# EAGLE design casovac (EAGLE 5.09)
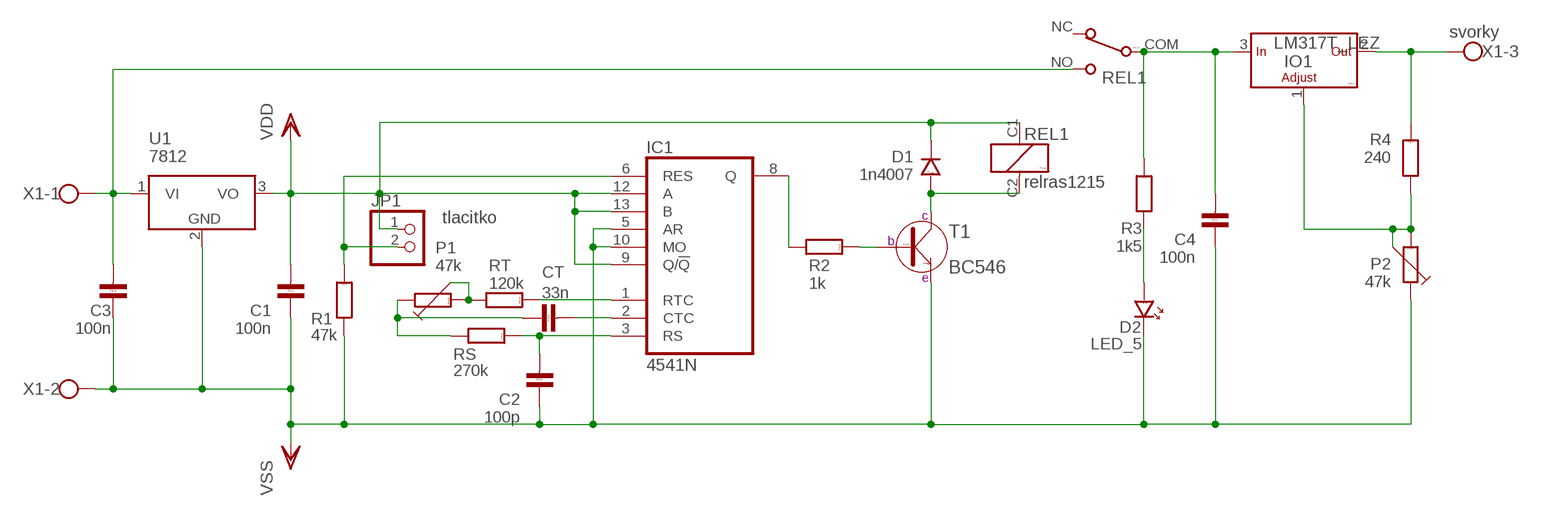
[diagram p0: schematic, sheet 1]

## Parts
C1  100n  C-KERAMIK_5  [C-5]
C2  100p  C-KERAMIK_5  [C-5]
C3  100n  C-KERAMIK_5  [C-5]
C4  100n  C-KERAMIK_5  [C-5]
CT  33n  C-KERAMIK_5  [C-5]
D1  1n4007  D_10  [D-10]
D2  LED_5  [LED_5]
IC1  4541N  [DIL14]
IO1  LM317T_LEZ  [TO-220]
JP1  tlacitko  PINHD-1X2  [1X02]
P1  47k  PT-10_V-LEZ  [PT10V]
P2  47k  PT-10_V-LEZ  [PT10V]
R1  47k  R_7,5  [R-7,5]
R2  1k  R_7,5  [R-7,5]
R3  1k5  R_7,5  [R-7,5]
R4  240  R_7,5  [R-7,5]
REL1  relras1215  RELRAS15  [RELE_RAS]
RS  270k  R_7,5  [R-7,5]
RT  120k  R_7,5  [R-7,5]
T1  BC546  [TO-92]
U1  7812  [TO-220S]
X1  svorky  W237-103  [W237-103]

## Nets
N$1: D1.A REL1.C2(RE:C2) T1.1(C)
N$2: IC1.6(RES) JP1.2 R1.2
N$3: IC1.8(Q) R2.1
N$4: R2.2 T1.2(B)
N$5: C2.2 IC1.3(RS) RS.2
N$6: IC1.1(RTC) RT.2
N$7: P1.2 P1.3 RT.1
N$8: CT.2 IC1.2(CTC)
N$9: CT.1 P1.1 RS.1
N$10: C3.2 REL1.NO(SW:NO) U1.1(VI) X1.1
N$11: C4.2 IO1.3(IN) R3.2 REL1.COM(SW:COM)
N$12: D2.A R3.1
N$13: IO1.2(OUT) R4.2 X1.3
N$14: IO1.1(ADJ) P2.2 P2.3 R4.1
VDD: C1.2 D1.K IC1.9(Q/!Q) IC1.12(A) IC1.13(B) JP1.1 REL1.C1(RE:C1) U1.3(VO)
VSS: C1.1 C2.1 C3.1 C4.1 D2.K IC1.5(AR) IC1.10(MO) P2.1 R1.1 T1.3(E) U1.2(GND) X1.2
Unconnected: REL1.NC(SW:NC)

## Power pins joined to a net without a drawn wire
VDD: IC1.14(VDD)
VSS: IC1.7(VSS)

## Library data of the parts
C1-C4 CT = #PaJa_21:C-KERAMIK: Kondenzator - keramicky
D1 = #PaJa_21:D: Dioda - univerzální
D2 = #PaJa_21:LED: LED - jednobarevna
IC1 = 45xx:4541: OSCILLATOR/PROGRAMMABLE TIMER
IO1 = #PaJa_21:LM317T: Stabilizator - s nastavitelnym napetim - 1,5A
JP1 = pinhead:PINHD-1X2: PIN HEADER
P1 P2 = #PaJa_21:PT-10: Trimr - 10,3mm
R1-R4 RS RT = #PaJa_21:R: Rezistor
REL1 = #PaJa_21:RELRAS??15: RELE - 1x prepinaci, 5V, 12V, 24V max. spinany proud = 15A
T1 = #PaJa_21:BC546: Tranzistor NPN - Univerzalni NF - Ic=0,1A
U1 = #_GM99:7812
X1 = con-wago-500:W237-103: WAGO SCREW CLAMP

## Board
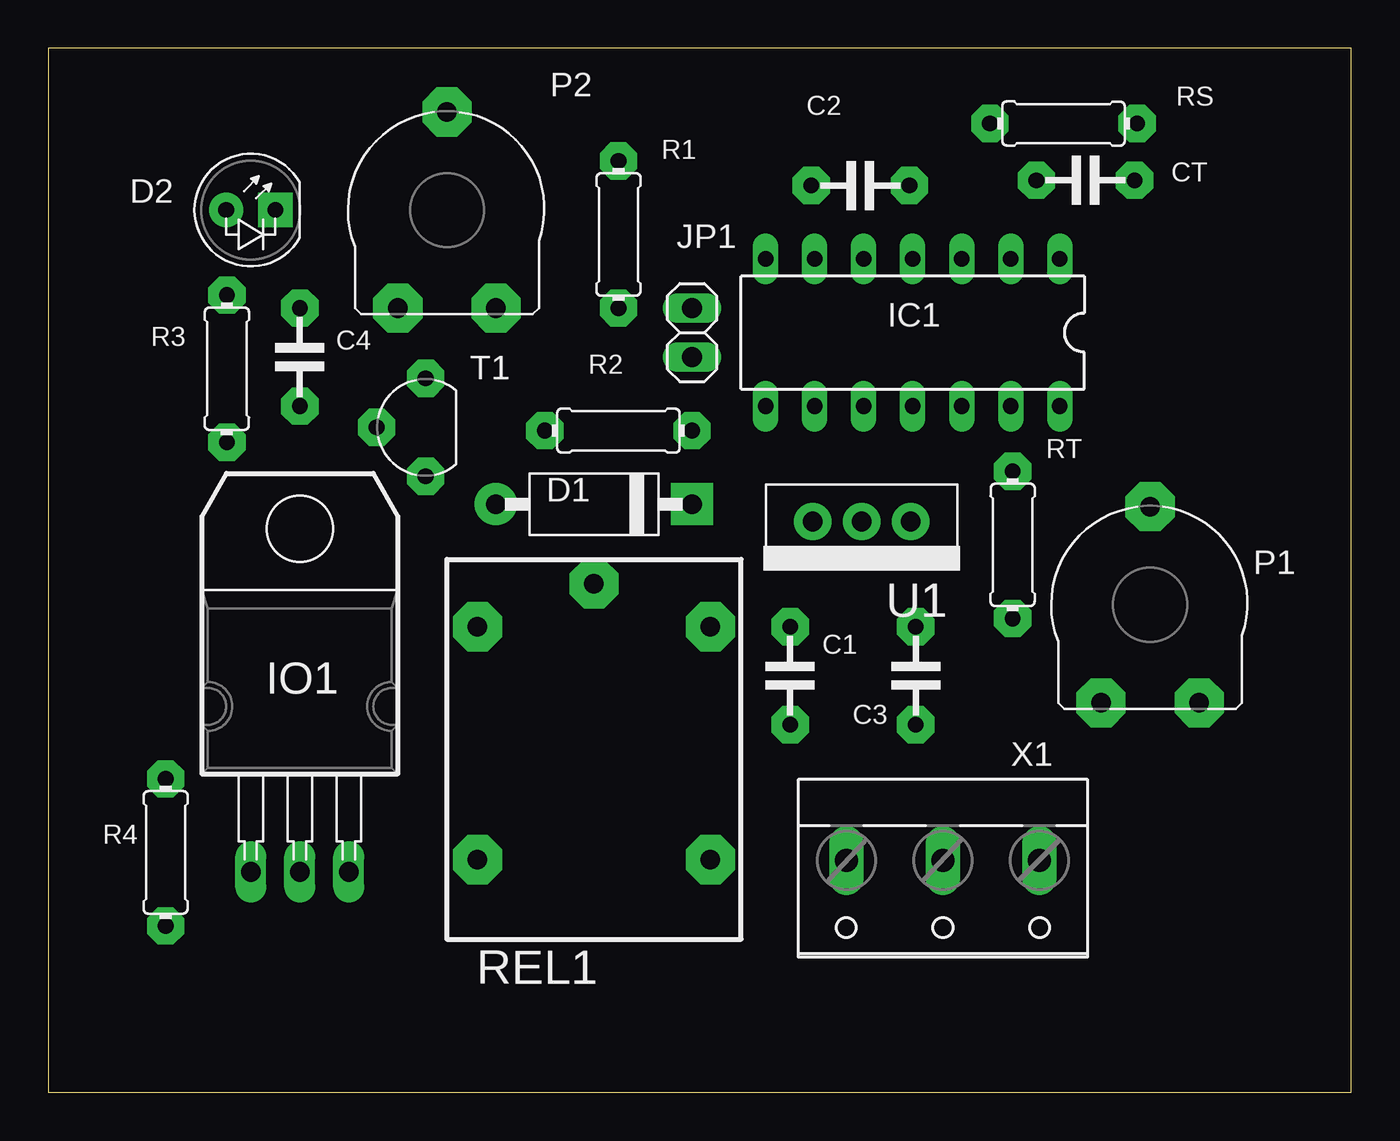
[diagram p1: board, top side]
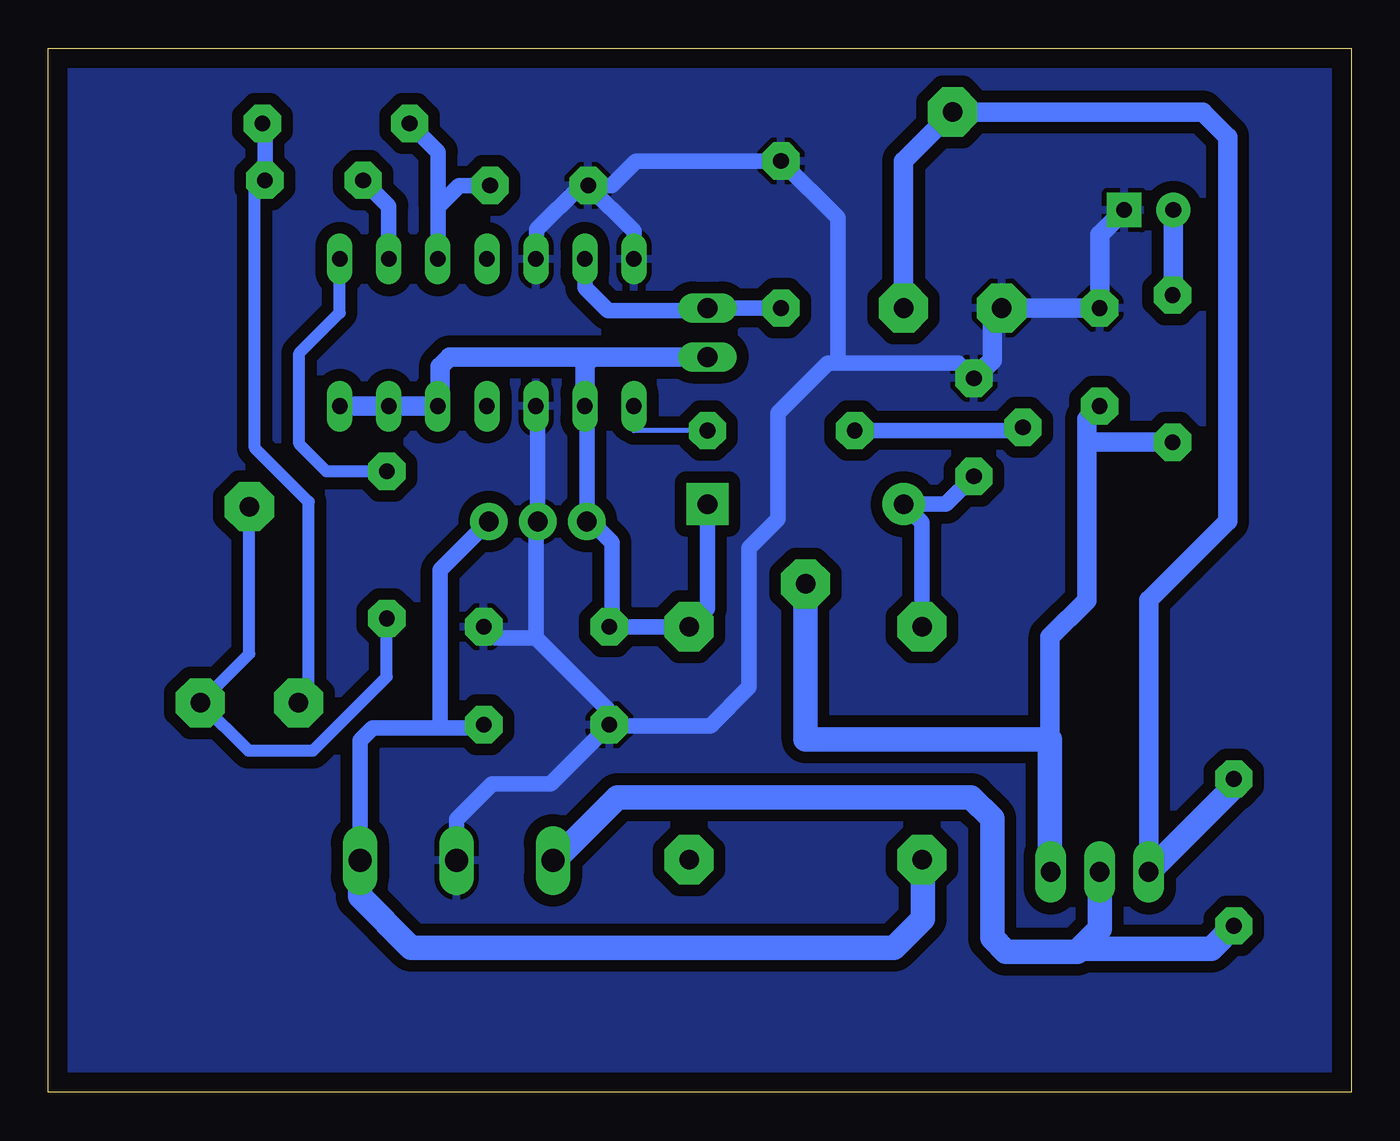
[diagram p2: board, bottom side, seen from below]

Size 67.5 x 54.1 mm. Coordinates in mm from the lower left corner, seen from the top.
Outline: 0,0 67.5,0 67.5,54.1 0,54.1 0,0
Copper layers (1*16): Top 0.035mm / dielectric 1.5mm / Bottom 0.035mm
Design rules "default": minimum track width 10mil, minimum drill 24mil, track to track 8mil, track to pad 8mil, pad to pad 8mil, via to via 8mil, smd to smd 8mil, copper to edge 40mil, drill to drill 8mil, minimum pad ring 10mil, minimum via ring 8mil, stop-mask expansion 4mil, vias tented up to drill 0mil, thermal gap 10mil

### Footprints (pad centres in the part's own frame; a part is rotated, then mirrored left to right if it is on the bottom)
C-5 = drill 0.813 pad 1.93 octagon: 1 -2.54,0; 2 2.54,0
D-10 = drill 1.016 pad 2.184 round: A -5.08,0 | drill 1.016 pad 2.184 square: K 5.08,0
LED_5 = drill 0.813 pad 1.778 round: A -1.27,0 | drill 0.813 pad 1.778 square: K 1.27,0
DIL14 = drill 0.813 long: 1 -7.62,-3.81; 2 -5.08,-3.81; 3 -2.54,-3.81; 4 0,-3.81; 5 2.54,-3.81; 6 5.08,-3.81; 7 7.62,-3.81; 8 7.62,3.81; 9 5.08,3.81; 10 2.54,3.81; 11 0,3.81; 12 -2.54,3.81; 13 -5.08,3.81; 14 -7.62,3.81
TO-220 = drill 1.016 pad 1.6 long: 1 -2.54,0; 2 0,0; 3 2.54,0
1X02 = drill 1.016 long: 1 -1.27,0; 2 1.27,0
PT10V = drill 1.016 pad 2.54 octagon: 1 -2.54,-5.08; 2 2.54,-5.08; 3 0,5.08
R-7,5 = drill 0.813 pad 1.93 octagon: 1 -3.81,0; 2 3.81,0
RELE_RAS = drill 1.016 pad 2.54 octagon: C1 -6.35,6.032; C2 -6.35,-6.032; COM -8.572,0; NC 5.715,6.032; NO 5.715,-6.032
TO-92 = drill 0.813 pad 1.93 octagon: 1 0,2.54; 2 2.54,0; 3 0,-2.54
TO-220S = drill 1.016 pad 1.93 round: 1 0,0; 2 2.54,0; 3 5.08,0
W237-103 = drill 1.194 long: 1 -5,-1.29; 2 0,-1.29; 3 5,-1.29

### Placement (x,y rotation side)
C1  38.43,21.59 90 top
C2  42.07,46.99 0 top
C3  44.94,21.59 270 top
C4  13.03,38.1 270 top
CT  53.73,47.26 180 top
D1  28.27,30.48 0 top
D2  10.49,45.72 0 top
IC1  44.78,39.37 180 top
IO1  13.03,11.43 0 top
JP1  33.35,39.37 90 top
P1  57.08,25.27 0 top
P2  20.65,45.72 0 top
R1  29.54,44.45 270 top
R2  29.54,34.29 180 top
R3  9.25,37.5 270 top
R4  6.08,12.44 270 top
REL1  28.27,17.78 270 top
RS  52.59,50.2 180 top
RT  49.96,28.37 90 top
T1  19.55,34.46 180 top
U1  44.68,29.58 180 top
X1  46.35,10.73 180 top

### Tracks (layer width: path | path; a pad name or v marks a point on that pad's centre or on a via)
N$1
  Bottom 0.813: T1.1 20.99,30.48 D1.A 22.24,29.53 REL1.C2
N$2
  Bottom 0.813: R1.2 JP1.2 33.49,40.5 38.5,40.5 39.7,41.7 IC1.6
N$3
  Bottom 0.254: IC1.8 37.16,34.29 R2.1
N$4
  Bottom 0.813: T1.2 17.18,34.29 R2.2
N$5
  Bottom 0.813: IC1.3 47.3,43.2 47.3,45.9 | 47.3,45.9 46.21,46.99 C2.2 | RS.2 47.3,48.72 47.3,45.9
N$6
  Bottom 0.61: IC1.1 52.4,40.4 54.5,38.3 54.5,33.6 53.08,32.18 RT.2
N$7
  Bottom 0.61: P1.3 57.08,22.73 P1.2 57.13,17.7 53.8,17.7 49.96,21.54 RT.1
N$8
  Bottom 0.813: CT.2 49.86,45.93 IC1.2
N$9
  Bottom 0.61: P1.1 54,20.73 54,30.6 56.8,33.4 56.8,46.73 CT.1
  Bottom 0.813: RS.1 56.27,50.07 CT.1
N$10
  Bottom 0.813: C3.2 45.09,18.9 47.2,18.9 | 47.2,18.9 50.7,18.9 51.35,18.25 X1.1 | U1.1 47.2,27.06 47.2,18.9
  Bottom 1.27: REL1.NO 22.2,12.03 22.2,9 23.7,7.5 48.7,7.5 51.35,10.15 X1.1
N$11
  Bottom 0.254: REL1.COM 28.27,25.4
  Bottom 1.016: 15.6,18.3 15.6,23.6 13.7,25.5 13.7,33.7 | 13.7,33.7 13.7,34.89 C4.2 | R3.2 13.69,33.69 13.7,33.7
  Bottom 1.27: IO1.3 15.6,11.43 15.6,18.3 28.27,18.3 REL1.COM
N$12
  Bottom 1.016: D2.A 9.22,41.34 R3.1
N$13
  Bottom 1.27: 13.1,11.43 IO1.2 13.03,8.47 14.05,7.45 | X1.3 41.28,12.02 38,15.3 19.7,15.3 18.6,14.2 18.6,8 17.9,7.3 14.2,7.3 14.05,7.45 | R4.2 7.26,7.45 14.05,7.45
N$14
  Bottom 1.016: IO1.1 10.49,25.51 6.4,29.6 6.4,49.5 7.7,50.8 P2.3 23.19,48.26 P2.2
  Bottom 1.27: IO1.1 6.08,15.84 R4.1
VDD
  Bottom 0.813: D1.K 33.35,25.08 REL1.C1 C1.2 38.3,24.26 38.3,28.5 39.38,29.58 U1.3 39.6,35.46 IC1.9
  Bottom 1.016: 39.1,38.1 39.3,38.1 39.7,37.7 IC1.9 | 39.1,38.1 JP1.1 | IC1.14 IC1.13 IC1.12 47.2,35.68 47.2,37.6 46.7,38.1 39.1,38.1
VSS
  Bottom 0.813: C1.1 38.38,19 33.2,19 31.2,21 31.2,28.2 29.7,29.7 29.7,35.2 27.1,37.8 26.6,37.8 | 26.6,37.8 20.35,37.8 T1.3 | C1.1 38.43,19.73 42.24,23.54 | IC1.10 42.14,35.46 U1.2 42.24,29.48 42.24,23.54 | C1.1 41.48,16 44.5,16 46.35,14.15 X1.2 | C3.1 44.35,23.54 42.24,23.54 | 26.6,37.8 26.6,45.32 R1.1 37.04,48.26 38.31,46.99 C2.1 | IC1.5 42.2,43.22 42.2,44.7 39.91,46.99 C2.1 | C2.1 37.16,44.62 IC1.7
  Bottom 1.016: T1.3 18.6,37.95 18.6,40.5 18.46,40.64 C4.1 13.03,44.45 D2.K
  pour Bottom (isolate 0.61): -4.9,-3.1 75.7,-3.1 75.7,60.4 -4.9,60.4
